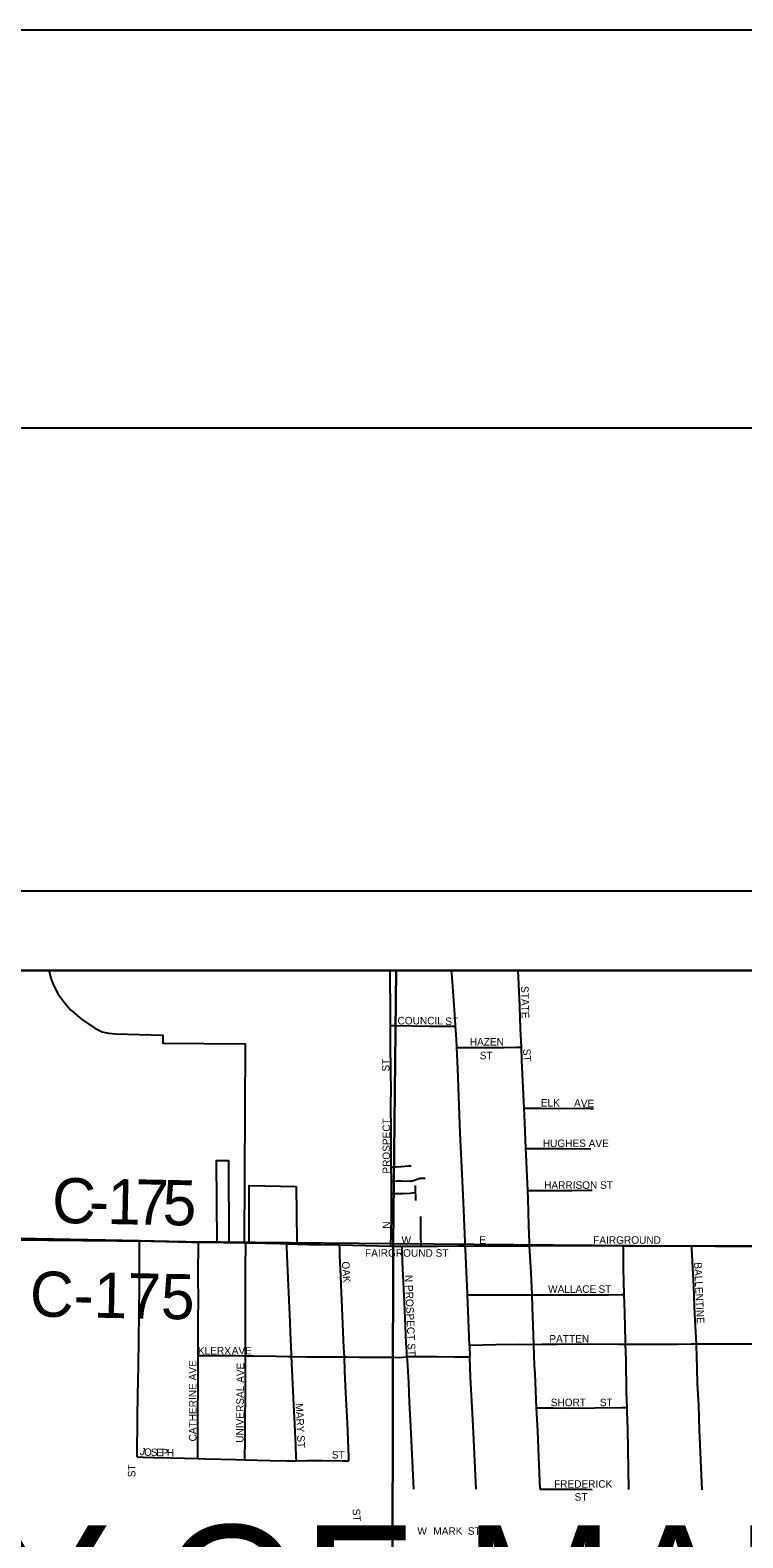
# Model space of a CAD drawing. Extents: x -97 to 34, y -21 to 22.
# Drawn here: x 5.142 to 6.037, y 20.104 to 22 of the extents above; entities that cross this region are included whole.
import ezdxf

# ---------------------------------------------------------------- set-up
doc = ezdxf.new("R2010")
doc.units = 0
for name, color, linetype in [('GM_X_City_Street', 7, 'Continuous'), ('GM_X_City_Street_Text', 7, 'Continuous'), ('GM_X_Corporation', 7, 'Continuous'), ('GM_X_County_Road', 7, 'Continuous'), ('GM_X_County_Road_Text', 7, 'Continuous'), ('GM_X_Section', 7, 'Continuous'), ('GM_X_State_Route', 7, 'Continuous'), ('GM_X_Township', 7, 'Continuous'), ('GM_X_Township_Text', 7, 'Continuous'), ('SH_Border', 7, 'Continuous'), ('SH_Cut_Line', 7, 'Continuous'), ('SH_Data', 7, 'Continuous')]:
    doc.layers.add(name, color=color, linetype=linetype)

msp = doc.modelspace()

# ---------------------------------------------------------------- linework, layer by layer
at = {"layer": 'GM_X_City_Street'}
for points in [[(5.5947, 20.7485), (5.5945, 20.7595), (5.5946, 20.775), (5.5943, 20.803), (5.5942, 20.8177)], [(5.7591, 20.7211), (5.7579, 20.7447), (5.7571, 20.7726), (5.7558, 20.8005), (5.7551, 20.8177)], [(5.5947, 20.7485), (5.6007, 20.7484), (5.6447, 20.7478), (5.6636, 20.7475), (5.6667, 20.7476), (5.6765, 20.7477)], [(5.5957, 20.5707), (5.5955, 20.5824), (5.5955, 20.598), (5.5955, 20.6104), (5.5956, 20.6197), (5.5953, 20.6446), (5.5954, 20.6725), (5.5953, 20.6849), (5.5947, 20.7315), (5.5947, 20.7471), (5.5947, 20.7485)], [(5.6779, 20.7208), (5.6954, 20.7209), (5.7065, 20.7209), (5.7264, 20.721), (5.7371, 20.721), (5.7536, 20.7211), (5.7591, 20.7211)], [(5.7626, 20.6444), (5.7599, 20.7044), (5.7591, 20.7211)], [(5.7626, 20.6444), (5.767, 20.6444), (5.7774, 20.6444), (5.7841, 20.6444), (5.806, 20.6442), (5.8371, 20.6445), (5.8433, 20.6445), (5.8466, 20.6443), (5.8496, 20.6442)], [(5.7649, 20.5941), (5.7633, 20.6269), (5.7626, 20.6444)], [(5.7649, 20.5941), (5.769, 20.594), (5.7814, 20.594), (5.8122, 20.5941), (5.8462, 20.5934)], [(5.7671, 20.541), (5.7659, 20.568), (5.7652, 20.5866), (5.7649, 20.5941)], [(5.5957, 20.5707), (5.6016, 20.571), (5.608, 20.5713), (5.6175, 20.5721), (5.6207, 20.5722)], [(5.5959, 20.5528), (5.5957, 20.5707)], [(5.5959, 20.5528), (5.5997, 20.553), (5.6031, 20.5532), (5.6059, 20.5531), (5.6087, 20.5531), (5.6196, 20.553), (5.6207, 20.5531), (5.6218, 20.5532), (5.6237, 20.5535), (5.6268, 20.5548), (5.628, 20.5553), (5.6289, 20.5556), (5.6303, 20.5561), (5.6315, 20.5565), (5.6331, 20.5567), (5.6353, 20.5567), (5.6383, 20.5568)], [(5.5961, 20.5374), (5.596, 20.5422), (5.5959, 20.5528)], [(5.5952, 20.4713), (5.5953, 20.4751), (5.5954, 20.4832), (5.5959, 20.511), (5.5961, 20.5173), (5.5961, 20.5297), (5.5961, 20.5359), (5.5961, 20.5374)], [(5.5961, 20.5374), (5.6011, 20.5373), (5.61, 20.5373), (5.6191, 20.5379), (5.622, 20.5382), (5.6262, 20.5386)], [(5.6262, 20.5386), (5.6259, 20.5474)], [(5.6265, 20.5284), (5.6264, 20.535), (5.6262, 20.5386)], [(5.7671, 20.541), (5.7724, 20.541), (5.8229, 20.5412), (5.8419, 20.5413), (5.8482, 20.5413)], [(5.7693, 20.4715), (5.7692, 20.4758), (5.7686, 20.497), (5.7675, 20.5308), (5.7671, 20.541)], [(5.6332, 20.4712), (5.6331, 20.4748), (5.6329, 20.4817), (5.6327, 20.4947), (5.6327, 20.5011), (5.6326, 20.5082)], [(5.2762, 20.2062), (5.2767, 20.2559), (5.2771, 20.2837), (5.2781, 20.3206), (5.2787, 20.3859), (5.2792, 20.4216), (5.2792, 20.4527), (5.2792, 20.4732), (5.2792, 20.4777)], [(5.353, 20.3335), (5.353, 20.3476), (5.3531, 20.3562), (5.3532, 20.3732), (5.3532, 20.3836), (5.3533, 20.3986), (5.3533, 20.4124), (5.3532, 20.4233), (5.3531, 20.4388), (5.3533, 20.4717), (5.3533, 20.4761)], [(5.4109, 20.4752), (5.4129, 20.4751)], [(5.4125, 20.3334), (5.4125, 20.3404), (5.4126, 20.3526), (5.4124, 20.3701), (5.4125, 20.3877), (5.4127, 20.4072), (5.4126, 20.4287), (5.4125, 20.4465), (5.4129, 20.4711), (5.4129, 20.4751)], [(5.4129, 20.4751), (5.4175, 20.4751)], [(5.4705, 20.3322), (5.4703, 20.3349), (5.4691, 20.363), (5.4686, 20.3756), (5.4679, 20.3944), (5.4658, 20.4402), (5.4649, 20.4594), (5.4645, 20.4711), (5.4643, 20.4741)], [(5.4776, 20.4738), (5.4921, 20.4734), (5.5076, 20.473), (5.5294, 20.4727), (5.5307, 20.4727)], [(5.5367, 20.3318), (5.5362, 20.3428), (5.5339, 20.3939), (5.5333, 20.4124), (5.5324, 20.4339), (5.5312, 20.4586), (5.5309, 20.4679), (5.5307, 20.4727)], [(5.5307, 20.4727), (5.5792, 20.4714), (5.5952, 20.4713)], [(5.5952, 20.4713), (5.6041, 20.4712), (5.6092, 20.4712)], [(5.6154, 20.3318), (5.615, 20.3377), (5.6147, 20.3445), (5.6144, 20.349), (5.6135, 20.3699), (5.6122, 20.4002), (5.6099, 20.4516), (5.6094, 20.4677), (5.6092, 20.4712)], [(5.6092, 20.4712), (5.6332, 20.4712)], [(5.6332, 20.4712), (5.6538, 20.4713), (5.6793, 20.4715), (5.6887, 20.4716)], [(5.6887, 20.4716), (5.7179, 20.4713), (5.7675, 20.4715), (5.7693, 20.4715)], [(5.7693, 20.4715), (5.8172, 20.4719), (5.8668, 20.4718), (5.8872, 20.4717)], [(5.7727, 20.41), (5.7723, 20.4193), (5.7715, 20.4375), (5.7693, 20.4715)], [(5.8884, 20.4103), (5.8876, 20.4432), (5.8873, 20.4682), (5.8872, 20.4717)], [(5.8872, 20.4717), (5.904, 20.4716), (5.9567, 20.4717), (5.973, 20.4717)], [(5.979, 20.3482), (5.9774, 20.3778), (5.9765, 20.3953), (5.9756, 20.4202), (5.974, 20.4519), (5.9732, 20.4685), (5.973, 20.4717)], [(5.973, 20.4717), (5.994, 20.4717), (6.0529, 20.4717), (6.0567, 20.4717)], [(5.6914, 20.4098), (5.7009, 20.4098), (5.7541, 20.4099), (5.7727, 20.41)], [(5.7727, 20.41), (5.8004, 20.4101), (5.8261, 20.4101), (5.8506, 20.4101), (5.8684, 20.4101), (5.8851, 20.4103), (5.8884, 20.4103)], [(5.7746, 20.3473), (5.7733, 20.395), (5.7727, 20.41)], [(5.8901, 20.3479), (5.8899, 20.3512), (5.889, 20.3873), (5.8884, 20.4103)], [(5.7746, 20.3473), (5.7849, 20.3477), (5.7908, 20.3479), (5.7973, 20.348), (5.8035, 20.348), (5.8345, 20.3481), (5.8809, 20.3479), (5.8901, 20.3479)], [(5.8901, 20.3479), (5.9273, 20.348), (5.9396, 20.348), (5.955, 20.348), (5.9735, 20.3481), (5.979, 20.3482)], [(5.892, 20.2683), (5.8914, 20.2881), (5.8906, 20.3282), (5.8901, 20.3479)], [(5.979, 20.3482), (6.0075, 20.3482), (6.0541, 20.3483), (6.0609, 20.3482)], [(5.9862, 20.1649), (5.9831, 20.2402), (5.9819, 20.2713), (5.9806, 20.2983), (5.9798, 20.318), (5.9791, 20.346), (5.979, 20.3482)], [(5.3524, 20.2041), (5.3524, 20.2076), (5.3525, 20.2218), (5.3526, 20.2398), (5.3527, 20.256), (5.3528, 20.2707), (5.3529, 20.2843), (5.3529, 20.3025), (5.3529, 20.3192), (5.353, 20.3335)], [(5.353, 20.3335), (5.3575, 20.3335), (5.4007, 20.3335), (5.4125, 20.3334)], [(5.4118, 20.2026), (5.4118, 20.2076), (5.4119, 20.2241), (5.4119, 20.2346), (5.4121, 20.2538), (5.4123, 20.2816), (5.4124, 20.294), (5.4125, 20.3155), (5.4125, 20.3279), (5.4125, 20.3334)], [(5.4125, 20.3334), (5.4224, 20.3334), (5.4513, 20.3326), (5.4665, 20.3323), (5.4705, 20.3322)], [(5.4705, 20.3322), (5.4895, 20.332), (5.5051, 20.332), (5.5367, 20.3318)], [(5.4764, 20.2014), (5.4762, 20.2061), (5.4757, 20.2198), (5.4744, 20.2477), (5.4736, 20.2632), (5.4705, 20.3322)], [(5.5367, 20.3318), (5.5396, 20.3318), (5.5552, 20.3317), (5.5798, 20.3315), (5.5957, 20.3314), (5.6059, 20.3313), (5.6154, 20.3318)], [(5.5425, 20.2014), (5.5423, 20.2057), (5.5405, 20.249), (5.5387, 20.2865), (5.5375, 20.3139), (5.5367, 20.3318)], [(5.7023, 20.1656), (5.6986, 20.2453), (5.6969, 20.2761), (5.6953, 20.3061), (5.6943, 20.3317)], [(5.7782, 20.268), (5.7867, 20.268), (5.7991, 20.2679), (5.8176, 20.2676), (5.8515, 20.2678), (5.8853, 20.2682), (5.892, 20.2683)], [(5.8943, 20.1653), (5.8928, 20.2416), (5.8922, 20.263), (5.892, 20.2683)], [(5.2762, 20.2062), (5.2841, 20.206), (5.2973, 20.2055), (5.3191, 20.2048), (5.3524, 20.2041)], [(5.3524, 20.2041), (5.3627, 20.2039), (5.4001, 20.2029), (5.4118, 20.2026)], [(5.4118, 20.2026), (5.4436, 20.2016), (5.4643, 20.2013), (5.4764, 20.2014)], [(5.4764, 20.2014), (5.4905, 20.2016)], [(5.4905, 20.2016), (5.4918, 20.2016), (5.5089, 20.2018), (5.5338, 20.2014), (5.5369, 20.2014), (5.5425, 20.2014)], [(5.7828, 20.1656), (5.7878, 20.1656), (5.7923, 20.1656), (5.8018, 20.1656), (5.8201, 20.1656), (5.841, 20.1655), (5.848, 20.1653)]]:
    msp.add_lwpolyline(points, dxfattribs=at)
at = {"layer": 'GM_X_Corporation'}
msp.add_line((6.8663, 20.8177), (5.1655, 20.8177), dxfattribs=at)
for points in [[(5.1655, 20.8177), (5.1656, 20.8168), (5.1673, 20.8099), (5.1686, 20.8056), (5.1709, 20.8007), (5.1732, 20.7952), (5.1772, 20.788), (5.1807, 20.783), (5.1863, 20.7756), (5.1926, 20.7684), (5.1971, 20.7644), (5.2038, 20.7588), (5.2076, 20.7557), (5.2232, 20.7454), (5.2281, 20.7426), (5.2323, 20.7406), (5.236, 20.7397), (5.2402, 20.7388), (5.2495, 20.738), (5.3086, 20.7363), (5.3086, 20.7264), (5.4119, 20.7253), (5.4109, 20.4752), (5.392, 20.4754), (5.3917, 20.5784), (5.3758, 20.5784), (5.3764, 20.4757), (5.3533, 20.4761), (5.2792, 20.4777), (5.1063, 20.481)], [(5.4763, 20.5462), (5.4769, 20.4776), (5.4769, 20.4741), (5.4769, 20.4738), (5.4769, 20.4738), (5.4768, 20.4738), (5.4568, 20.4743), (5.4404, 20.4745), (5.4239, 20.4748), (5.4168, 20.4749), (5.4169, 20.4787), (5.4173, 20.5473), (5.4763, 20.5462)]]:
    msp.add_lwpolyline(points, dxfattribs=at)
at = {"layer": 'GM_X_County_Road'}
for points in [[(5.1063, 20.481), (5.1106, 20.4809), (5.1418, 20.4805), (5.2011, 20.4794), (5.2759, 20.4778), (5.2792, 20.4777)], [(5.2792, 20.4777), (5.3446, 20.4762), (5.3533, 20.4761)], [(5.3533, 20.4761), (5.3851, 20.4756), (5.4109, 20.4752)], [(5.4175, 20.4751), (5.4565, 20.4743), (5.4643, 20.4741)], [(5.4643, 20.4741), (5.4776, 20.4738)]]:
    msp.add_lwpolyline(points, dxfattribs=at)
at = {"layer": 'GM_X_Section'}
for p, q in [((5.6017, 20.8177), (4.6026, 20.8177)), ((6.6134, 20.8177), (5.6017, 20.8177))]:
    msp.add_line(p, q, dxfattribs=at)
for points in [[(4.6026, 20.8177), (4.5991, 20.484), (5.598, 20.4746), (5.6017, 20.8177)], [(5.6017, 20.8177), (5.598, 20.4746), (6.6105, 20.4661), (6.6134, 20.8177)]]:
    msp.add_lwpolyline(points, dxfattribs=at)
for points in [[(4.5991, 20.484), (5.598, 20.4746), (5.5961, 19.4736), (4.5986, 19.4785)], [(5.598, 20.4746), (6.6105, 20.4661), (6.6081, 19.4622), (5.5961, 19.4736)]]:
    msp.add_lwpolyline(points, close=True, dxfattribs=at)
at = {"layer": 'GM_X_State_Route'}
for points in [[(5.6885, 20.4766), (5.686, 20.5356), (5.6824, 20.6133), (5.6791, 20.6942), (5.6779, 20.7208), (5.6775, 20.7315), (5.6765, 20.7477), (5.676, 20.7564), (5.6722, 20.8092), (5.6715, 20.8177)], [(5.6938, 20.3462), (5.6927, 20.3791), (5.6914, 20.4098), (5.6913, 20.4112), (5.6889, 20.4672), (5.6887, 20.4716), (5.6885, 20.4766)], [(5.6938, 20.3462), (5.6943, 20.3317), (5.6833, 20.3316)], [(5.7746, 20.3473), (5.7694, 20.3472), (5.7549, 20.3473), (5.7271, 20.347), (5.6938, 20.3462)], [(5.7828, 20.1656), (5.7812, 20.2064), (5.7796, 20.2386), (5.7782, 20.268), (5.7768, 20.2996), (5.7763, 20.3108), (5.7757, 20.3216), (5.7751, 20.3336), (5.7746, 20.3473)], [(5.6833, 20.3316), (5.6744, 20.3316), (5.6524, 20.3318), (5.6302, 20.332), (5.6214, 20.332), (5.6154, 20.3318), (5.6158, 20.3276), (5.6168, 20.3069)], [(5.6168, 20.3069), (5.6172, 20.2996), (5.6182, 20.2748), (5.6197, 20.2445), (5.6236, 20.1655)]]:
    msp.add_lwpolyline(points, dxfattribs=at)
at = {"layer": 'GM_X_Township'}
msp.add_lwpolyline([(8.6417, 20.8177), (3.5515, 20.8177), (3.5515, 17.4809)], dxfattribs=at)
at = {"layer": 'SH_Border'}
msp.add_lwpolyline([(2, 21.5), (33.5, 21.5), (33.5, 0.5), (2, 0.5)], close=True, dxfattribs=at)
at = {"layer": 'SH_Cut_Line'}
msp.add_lwpolyline([(0, 0), (34, 0), (34, 22), (0, 22)], close=True, dxfattribs=at)
at = {"layer": 'SH_Data'}
for p, q in [((3.4515, 20.9177), (10.4515, 20.9177)), ((3.5515, 20.8177), (10.3515, 20.8177))]:
    msp.add_line(p, q, dxfattribs=at)

# ---------------------------------------------------------------- texts
at = {"layer": 'GM_X_City_Street_Text'}
for s, rotation, p in [('STATE', 271.3315, (5.7586, 20.7981)), ('COUNCIL', 0, (5.6035, 20.7499)), ('ST', 0, (5.6635, 20.7491)), ('HAZEN', 0, (5.6943, 20.7232)), ('ST', 90, (5.5934, 20.6906)), ('ST', 0, (5.7068, 20.7061)), ('ST', 273.365, (5.7611, 20.719)), ('ELK', 0, (5.7835, 20.6466)), ('A', 357.836, (5.8252, 20.6466)), ('V', 357.8424, (5.8336, 20.6462)), ('E', 358.3866, (5.842, 20.6459)), ('PROSPECT', 90, (5.5942, 20.5623)), ('HUGHES AVE', 0, (5.786, 20.5957)), ('HARRISON ST', 0, (5.7877, 20.5432)), ('N', 90, (5.5942, 20.4931)), ('W', 0, (5.6085, 20.4741)), ('E', 0, (5.706, 20.4741)), ('FAIRGROUND', 0, (5.8493, 20.4741)), ('FAIRGROUND ST', 0, (5.5627, 20.4578)), ('OAK', 273.8194, (5.5336, 20.4516)), ('BALLENTINE', 272.6308, (5.9761, 20.4506)), ('N PROSPECT ST', 272.2451, (5.6128, 20.4348)), ('WALLACE', 0, (5.7927, 20.4124)), ('ST', 0, (5.856, 20.4124)), ('PATTEN', 0, (5.7943, 20.3499)), ('KLERX', 0, (5.3527, 20.3349)), ('AVE', 0, (5.3952, 20.3349)), ('CATHERINE AVE', 90, (5.3509, 20.2256)), ('UNIVERSAL AVE', 89.489, (5.41, 20.2239)), ('MARY ST', 272.8176, (5.4753, 20.2732)), ('SHORT', 0, (5.796, 20.2699)), ('ST', 0, (5.8577, 20.2699)), ('J', 347.5328, (5.2791, 20.209)), ('O', 355.759, (5.2847, 20.2078)), ('S', 358.7763, (5.2935, 20.2072)), ('E', 358.7707, (5.3002, 20.2071)), ('P', 358.8012, (5.3069, 20.2069)), ('H', 358.776, (5.3135, 20.2068)), ('ST', 0, (5.521, 20.2041)), ('ST', 90, (5.2742, 20.1806)), ('FREDERICK', 0, (5.8002, 20.1674)), ('ST', 0, (5.826, 20.1511)), ('ST', 273.5746, (5.5469, 20.1407)), ('W', 0, (5.6285, 20.1082)), ('MARK', 0, (5.6485, 20.1082)), ('ST', 0, (5.6918, 20.1082)), ('E', 0, (5.7252, 20.1082))]:
    msp.add_text(s, height=0.00947, rotation=rotation, dxfattribs=at).set_placement(p)
at = {"layer": 'GM_X_County_Road_Text'}
for s, height, rotation, p in [('C', 0.0568, 358.8645, (5.1691, 20.5004)), ('1', 0.0568, 358.8645, (5.2385, 20.499)), ('7', 0.0568, 358.865, (5.2733, 20.4984)), ('5', 0.0568, 358.8825, (5.308, 20.4977)), ('-', 0.0568, 358.8645, (5.2154, 20.4995)), ('C-175', 0.05682, 358.9035, (5.1412, 20.3828))]:
    msp.add_text(s, height=height, rotation=rotation, dxfattribs=at).set_placement(p)
at = {"layer": 'GM_X_Township_Text'}
msp.add_text('CITY OF MARION', height=0.170455, rotation=0, dxfattribs=at).set_placement((4.724, 19.9498))

doc.saveas('drawing.dxf')
